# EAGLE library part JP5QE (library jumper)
JUMPER
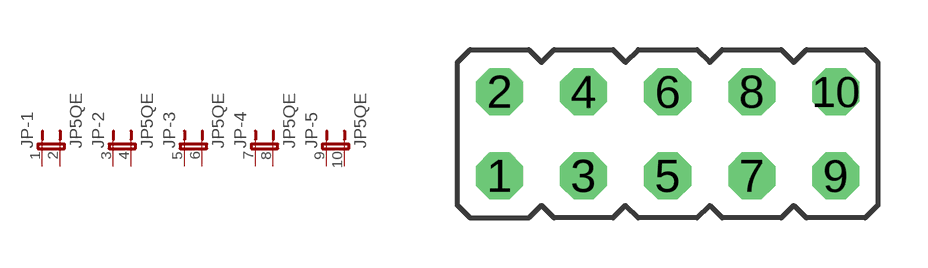
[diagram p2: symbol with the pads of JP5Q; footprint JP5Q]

Designator prefix JP; gates -1=JP2E -2=JP2E -3=JP2E -4=JP2E -5=JP2E

## JP5QE  [JP5Q]
1  -1:1  pas
2  -1:2  pas
3  -2:1  pas
4  -2:2  pas
5  -3:1  pas
6  -3:2  pas
7  -4:1  pas
8  -4:2  pas
9  -5:1  pas
10  -5:2  pas

## Footprint JP5Q (pad centres in mm)
JUMPER
drill 0.914 octagon: 1 -5.08,-1.27; 2 -5.08,1.27; 3 -2.54,-1.27; 4 -2.54,1.27; 5 0,-1.27; 6 0,1.27; 7 2.54,-1.27; 8 2.54,1.27; 9 5.08,-1.27; 10 5.08,1.27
